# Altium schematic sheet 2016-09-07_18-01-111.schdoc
size 316 x 111 mm; SheetNumber: 1; SheetTotal: 1
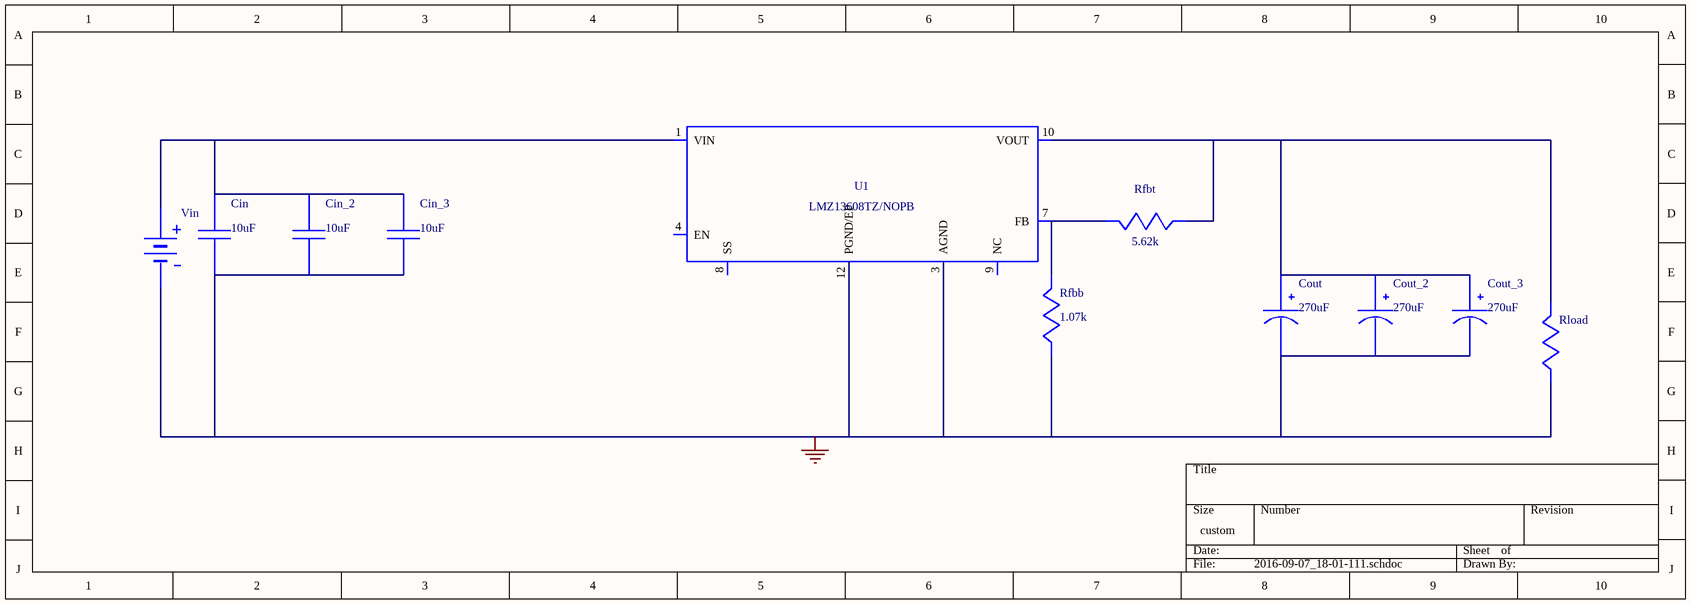
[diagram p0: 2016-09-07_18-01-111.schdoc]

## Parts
Cin  value 10uF  (hidden comment: GRM32ER7YA106KA12L)
Cin_2  value 10uF  (hidden comment: GRM32ER7YA106KA12L)
Cin_3  value 10uF  (hidden comment: GRM32ER7YA106KA12L)
Cout  value 270uF  (hidden comment: 16SVPG270M)
Cout_2  value 270uF  (hidden comment: 16SVPG270M)
Cout_3  value 270uF  (hidden comment: 16SVPG270M)
Rfbb  value 1.07k  (hidden comment: ERJ-6ENF1071V)
Rfbt  value 5.62k  (hidden comment: ERJ-6ENF5621V)
Rload  WB_LOAD_RESISTOR  (value not drawn)
U1  LMZ13608TZ/NOPB
Vin  WB_BATTERY  (value not drawn)

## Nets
0: Cin.2 Cin_2.2 Cin_3.2 Cout.2(-) Cout_2.2(-) Cout_3.2(-) Rfbb.2 Rload.2 U1.3(AGND) U1.5(AGND) U1.6(AGND) U1.12(PGND/EP) Vin.2(-)
NetCin_1: Cin.1 Cin_2.1 Cin_3.1 U1.1(VIN) U1.2(VIN) Vin.1(+)
NetCout_1: Cout.1(+) Cout_2.1(+) Cout_3.1(+) Rfbt.2 Rload.1 U1.10(VOUT) U1.11(VOUT)
NetRfbb_1: Rfbb.1 Rfbt.1 U1.7(FB)

Not connected (* = marked no-connect by the designer): U1 4(EN) 8(SS) 9(NC)

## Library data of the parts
Cin Cin_2 Cin_3 = GRM32ER7YA106KA12L: GRM32ER7YA106KA1; Manufacturer Name: MuRata
Cout Cout_2 Cout_3 = 16SVPG270M: Manufacturer Name: Panasonic
Rfbb = ERJ-6ENF1071V: Manufacturer Name: Panasonic
Rfbt = ERJ-6ENF5621V: Manufacturer Name: Panasonic
U1 = LMZ13608TZ/NOPB: Manufacturer Name: Texas Instruments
